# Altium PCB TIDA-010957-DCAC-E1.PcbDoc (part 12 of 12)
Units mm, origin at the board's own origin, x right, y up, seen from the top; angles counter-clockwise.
Board outline 300 x 300 mm, 4 copper layers (Top Layer, Layer 1, Layer 2, Bottom Layer), stack 1.787 mm thick; 1159 components, 619 nets, 3431 pads, 2942 vias.
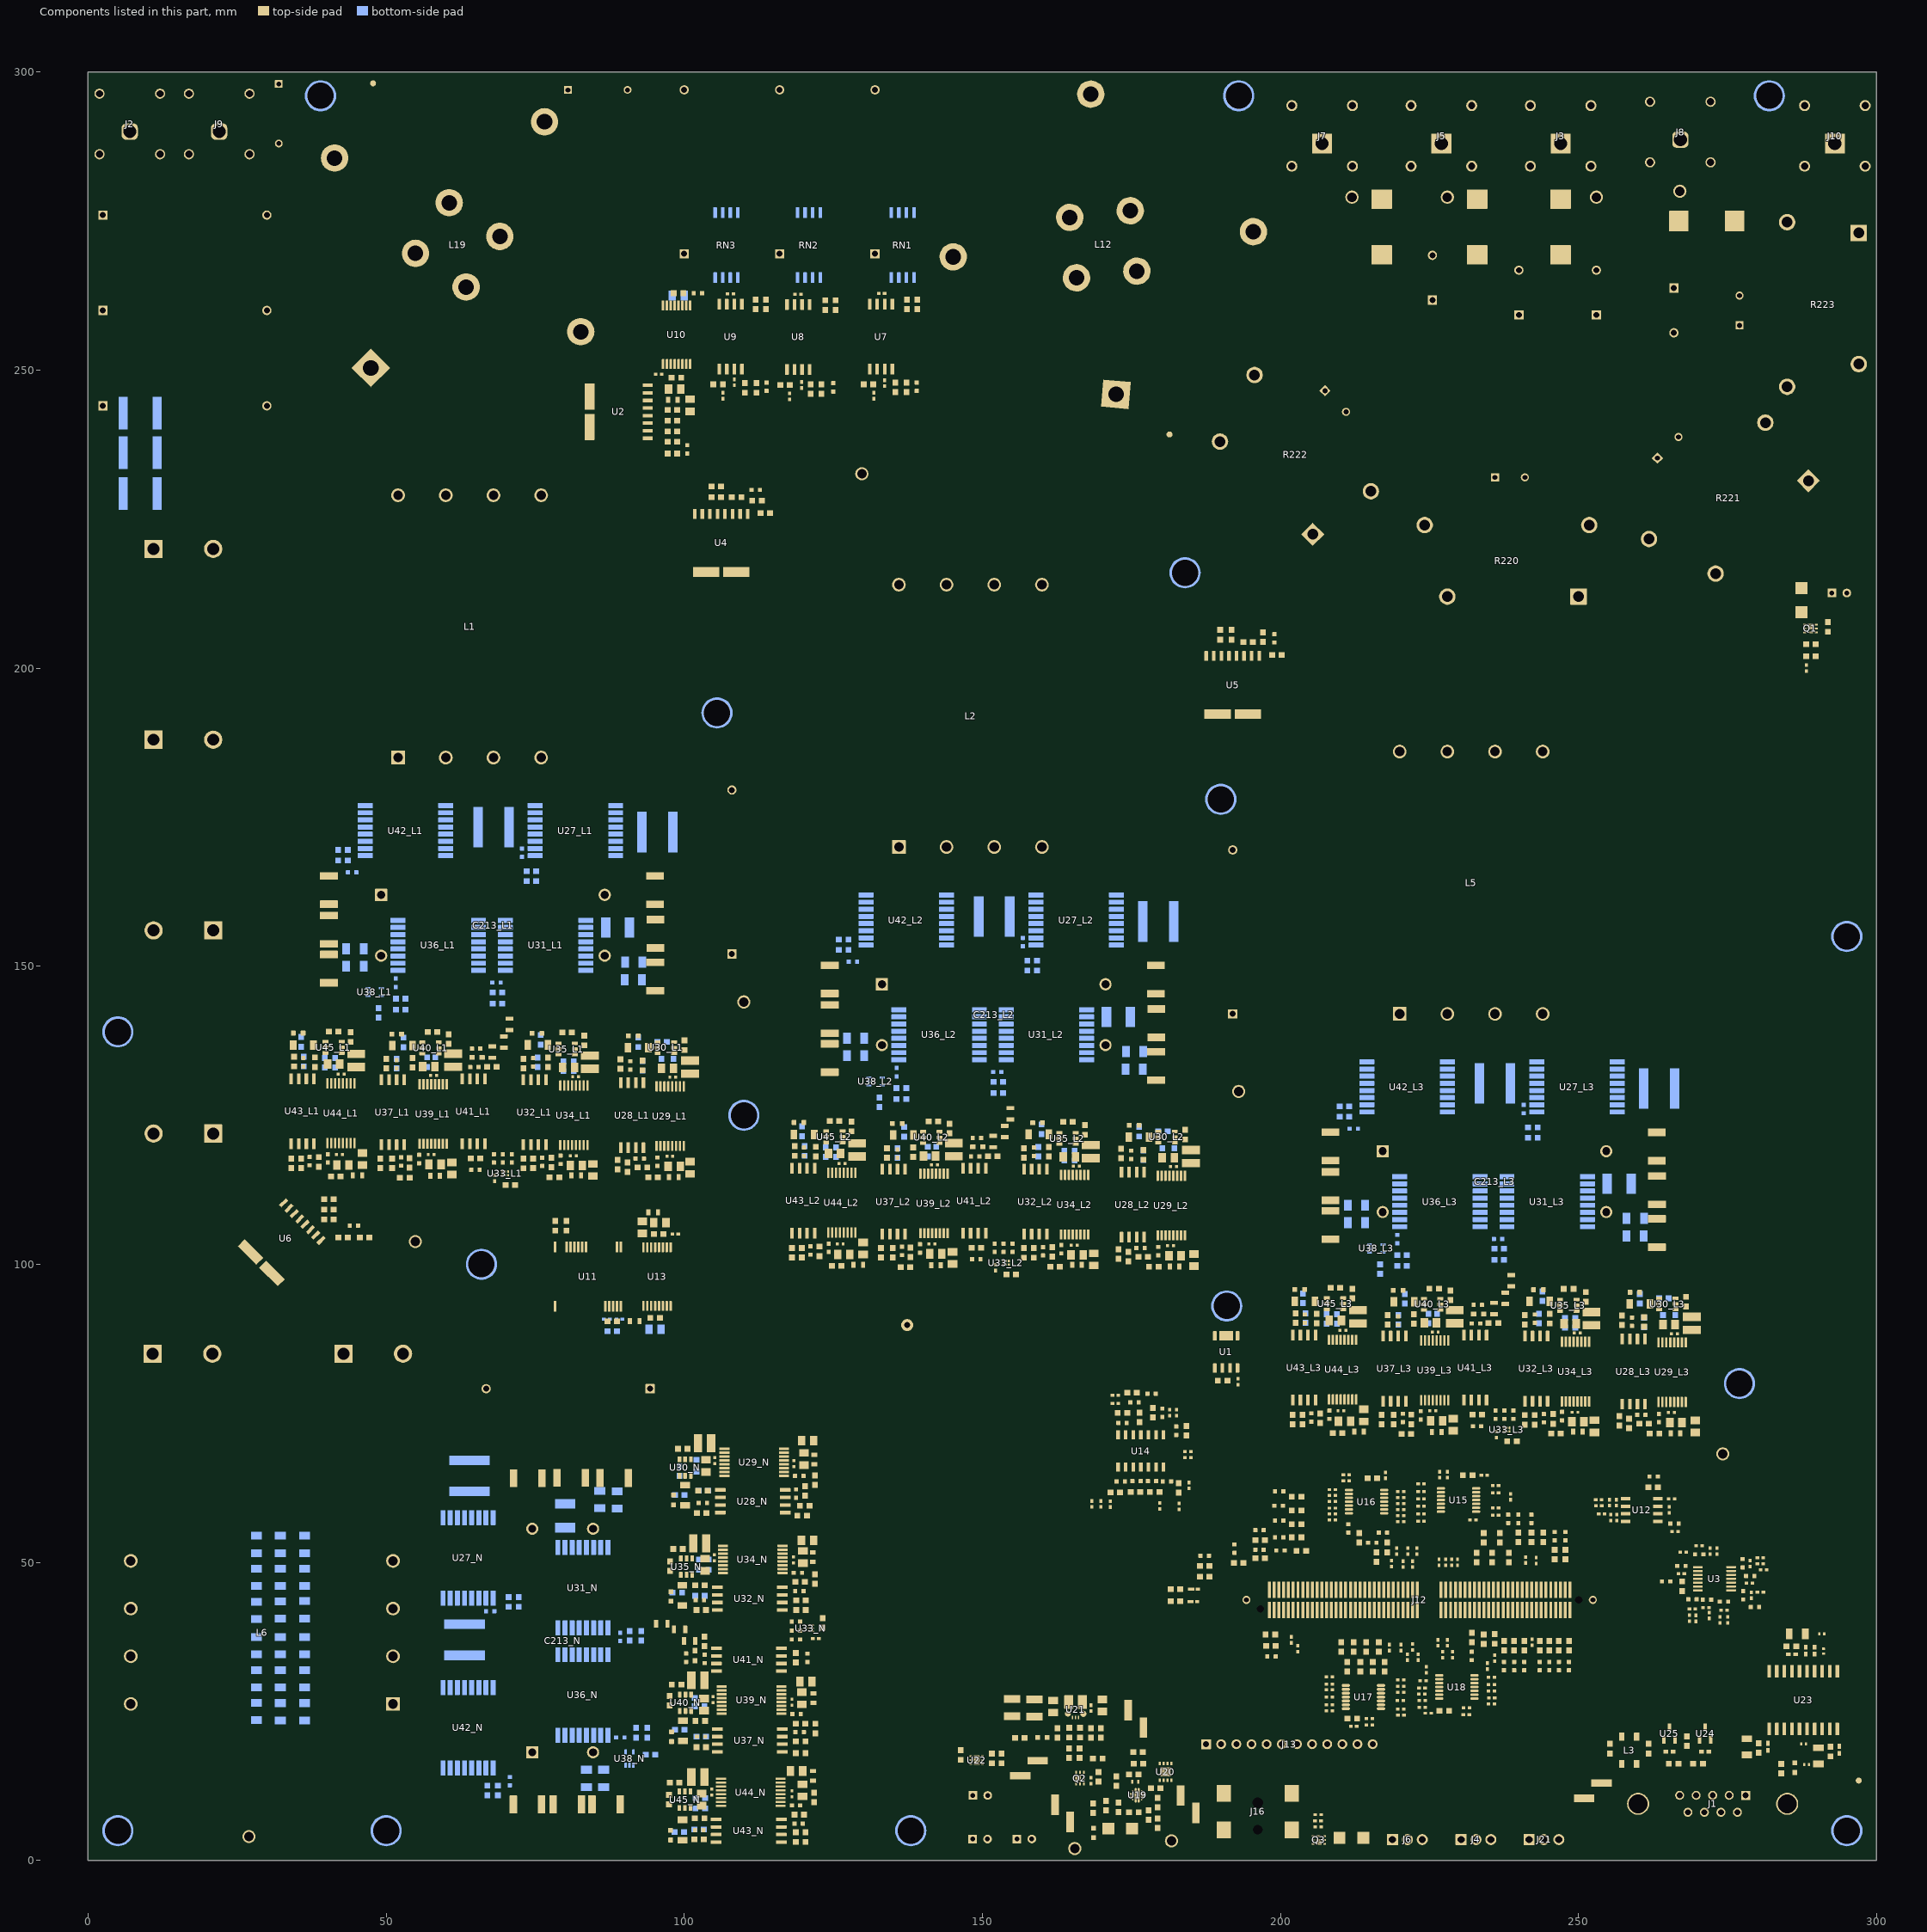
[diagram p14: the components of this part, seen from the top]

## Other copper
Top Layer:
  pour cut-out: 287.687,154.526 ccw(c294.987,154.526) 294.987,147.226 ccw(c294.987,154.526) 302.287,154.526 ccw(c294.987,154.526) 294.987,161.826 ccw(c294.987,154.526)
  pour cut-out: 185.787,295.826 ccw(c193.087,295.826) 193.087,288.526 ccw(c193.087,295.826) 200.387,295.826 ccw(c193.087,295.826) 193.087,303.126 ccw(c193.087,295.826)
  pour cut-out: 176.787,215.826 ccw(c184.087,215.826) 184.087,208.526 ccw(c184.087,215.826) 191.387,215.826 ccw(c184.087,215.826) 184.087,223.126 ccw(c184.087,215.826)
  pour cut-out: 98.287,192.326 ccw(c105.587,192.326) 105.587,185.026 ccw(c105.587,192.326) 112.887,192.326 ccw(c105.587,192.326) 105.587,199.626 ccw(c105.587,192.326)
  pour cut-out: 182.762,177.641 ccw(c190.062,177.641) 190.062,170.341 ccw(c190.062,177.641) 197.362,177.641 ccw(c190.062,177.641) 190.062,184.941 ccw(c190.062,177.641)
  pour cut-out: 287.787,4.826 ccw(c295.087,4.826) 295.087,-2.474 ccw(c295.087,4.826) 302.387,4.826 ccw(c295.087,4.826) 295.087,12.126 ccw(c295.087,4.826)
  pour cut-out: 102.787,124.826 ccw(c110.087,124.826) 110.087,117.526 ccw(c110.087,124.826) 117.387,124.826 ccw(c110.087,124.826) 110.087,132.126 ccw(c110.087,124.826)
  pour cut-out: 58.787,99.826 ccw(c66.087,99.826) 66.087,92.526 ccw(c66.087,99.826) 73.387,99.826 ccw(c66.087,99.826) 66.087,107.126 ccw(c66.087,99.826)
  pour cut-out: -2.213,4.826 ccw(c5.087,4.826) 5.087,-2.474 ccw(c5.087,4.826) 12.387,4.826 ccw(c5.087,4.826) 5.087,12.126 ccw(c5.087,4.826)
  pour cut-out: 42.487,3.726 ccw(c49.787,3.726) 49.787,-3.574 ccw(c49.787,3.726) 57.087,3.726 ccw(c49.787,3.726) 49.787,11.026 ccw(c49.787,3.726)
  pour cut-out: 130.687,4.526 ccw(c137.987,4.526) 137.987,-2.774 ccw(c137.987,4.526) 145.287,4.526 ccw(c137.987,4.526) 137.987,11.826 ccw(c137.987,4.526)
  pour cut-out: 269.787,79.826 ccw(c277.087,79.826) 277.087,72.526 ccw(c277.087,79.826) 284.387,79.826 ccw(c277.087,79.826) 277.087,87.126 ccw(c277.087,79.826)
  pour cut-out: -2.994,139.199 ccw(c4.306,139.199) 4.306,131.899 ccw(c4.306,139.199) 11.606,139.199 ccw(c4.306,139.199) 4.306,146.499 ccw(c4.306,139.199)
  pour cut-out: 187.246,190.135 186.958,190.135 186.958,193.081 187.246,193.081
  pour cut-out: 101.456,213.97 101.168,213.97 101.168,216.916 101.456,216.916
  pour cut-out: 188.1,99.2 185.8,99.2 183.7,97.1 183.7,87.5 186.1,85.1 188.1,85.1
  pour cut-out: 31.444,95.548 31.241,95.752 33.324,97.835 33.527,97.631
  pour cut-out: 24.174,102.083 23.971,102.286 26.342,104.658 26.546,104.454
  pour cut-out: 19,82 22.5,82 24.096,83.596 24.096,86.404 22.5,88 19,88 17.596,86.596 17.596,83.404
  pour cut-out: 81.97,247.754 81.97,248.042 84.916,248.042 84.916,247.754
  pour cut-out: 81.983,237.968 81.983,238.256 84.929,238.256 84.929,237.968
  pour cut-out: 111.232,214.033 110.944,214.033 110.944,216.979 111.232,216.979
  pour cut-out: 197.032,190.158 196.744,190.158 196.744,193.104 197.032,193.104
  pour cut-out: 7.75,217 14.25,217 14.25,223 7.75,223
  pour cut-out: 7.75,185 14.25,185 14.25,191 7.75,191
  pour cut-out: 7.75,153 14.25,153 14.25,159 7.75,159
  pour cut-out: 7.75,118.936 14.25,118.936 14.25,124.936 7.75,124.936
  pour cut-out: 48.334,80.5 57.834,80.5 57.834,89.463 48.334,89.463
  pour cut-out: 16.5,117.436 26,117.436 26,126.399 16.5,126.399
  pour cut-out: 16.5,215.5 26,215.5 26,224.463 16.5,224.463
  pour cut-out: 16.5,183.5 26,183.5 26,192.463 16.5,192.463
  pour cut-out: 18.5,151.5 24,151.5 26,153.5 26,158.5 24.037,160.463 18.463,160.463 16.5,158.5 16.5,153.5
  text ".Layer_Name" at 169.75,-14.25 h1.52
Layer 1:
  pour cut-out: -3.016,139.284 ccw(c4.284,139.284) 4.284,131.984 ccw(c4.284,139.284) 11.584,139.284 ccw(c4.284,139.284) 4.284,146.584 ccw(c4.284,139.284)
  pour cut-out: 287.74,154.548 ccw(c295.04,154.548) 295.04,147.248 ccw(c295.04,154.548) 302.34,154.548 ccw(c295.04,154.548) 295.04,161.848 ccw(c295.04,154.548)
  pour cut-out: 274.84,295.848 ccw(c282.14,295.848) 282.14,288.548 ccw(c282.14,295.848) 289.44,295.848 ccw(c282.14,295.848) 282.14,303.148 ccw(c282.14,295.848)
  pour cut-out: 185.84,295.848 ccw(c193.14,295.848) 193.14,288.548 ccw(c193.14,295.848) 200.44,295.848 ccw(c193.14,295.848) 193.14,303.148 ccw(c193.14,295.848)
  pour cut-out: 31.884,296.035 ccw(c39.184,296.035) 39.184,288.735 ccw(c39.184,296.035) 46.484,296.035 ccw(c39.184,296.035) 39.184,303.335 ccw(c39.184,296.035)
  pour cut-out: 176.84,215.848 ccw(c184.14,215.848) 184.14,208.548 ccw(c184.14,215.848) 191.44,215.848 ccw(c184.14,215.848) 184.14,223.148 ccw(c184.14,215.848)
  pour cut-out: 287.84,4.848 ccw(c295.14,4.848) 295.14,-2.452 ccw(c295.14,4.848) 302.44,4.848 ccw(c295.14,4.848) 295.14,12.148 ccw(c295.14,4.848)
  pour cut-out: 183.74,93.148 ccw(c191.04,93.148) 191.04,85.848 ccw(c191.04,93.148) 198.34,93.148 ccw(c191.04,93.148) 191.04,100.448 ccw(c191.04,93.148)
  pour cut-out: 102.84,124.848 ccw(c110.14,124.848) 110.14,117.548 ccw(c110.14,124.848) 117.44,124.848 ccw(c110.14,124.848) 110.14,132.148 ccw(c110.14,124.848)
  pour cut-out: 58.84,99.848 ccw(c66.14,99.848) 66.14,92.548 ccw(c66.14,99.848) 73.44,99.848 ccw(c66.14,99.848) 66.14,107.148 ccw(c66.14,99.848)
  pour cut-out: -2.16,4.848 ccw(c5.14,4.848) 5.14,-2.452 ccw(c5.14,4.848) 12.44,4.848 ccw(c5.14,4.848) 5.14,12.148 ccw(c5.14,4.848)
  pour cut-out: 42.54,3.748 ccw(c49.84,3.748) 49.84,-3.552 ccw(c49.84,3.748) 57.14,3.748 ccw(c49.84,3.748) 49.84,11.048 ccw(c49.84,3.748)
  pour cut-out: 130.74,4.548 ccw(c138.04,4.548) 138.04,-2.752 ccw(c138.04,4.548) 145.34,4.548 ccw(c138.04,4.548) 138.04,11.848 ccw(c138.04,4.548)
  pour cut-out: 269.772,79.87 ccw(c277.072,79.87) 277.072,72.57 ccw(c277.072,79.87) 284.372,79.87 ccw(c277.072,79.87) 277.072,87.17 ccw(c277.072,79.87)
  pour cut-out: 185,175 185,181.5 187,183.5 193.5,183.5 195,182 195,175 193,173 187,173
  pour cut-out: 100.5,189 100.5,196.5 102,198 109,198 110.5,196.5 110.5,189 109,187.5 102,187.5
  pour cut-out: 249.7,260.2 249.7,259.3 252.7,256.3 256.4,256.3 256.5,256.4 249.7,263.2
Layer 2:
  pour cut-out: -2.99,139.283 ccw(c4.31,139.283) 4.31,131.983 ccw(c4.31,139.283) 11.61,139.283 ccw(c4.31,139.283) 4.31,146.583 ccw(c4.31,139.283)
  pour cut-out: 287.761,154.533 ccw(c295.061,154.533) 295.061,147.233 ccw(c295.061,154.533) 302.361,154.533 ccw(c295.061,154.533) 295.061,161.833 ccw(c295.061,154.533)
  pour cut-out: 274.861,295.833 ccw(c282.161,295.833) 282.161,288.533 ccw(c282.161,295.833) 289.461,295.833 ccw(c282.161,295.833) 282.161,303.133 ccw(c282.161,295.833)
  pour cut-out: 185.861,295.833 ccw(c193.161,295.833) 193.161,288.533 ccw(c193.161,295.833) 200.461,295.833 ccw(c193.161,295.833) 193.161,303.133 ccw(c193.161,295.833)
  pour cut-out: 176.861,215.833 ccw(c184.161,215.833) 184.161,208.533 ccw(c184.161,215.833) 191.461,215.833 ccw(c184.161,215.833) 184.161,223.133 ccw(c184.161,215.833)
  pour cut-out: 287.861,4.833 ccw(c295.161,4.833) 295.161,-2.467 ccw(c295.161,4.833) 302.461,4.833 ccw(c295.161,4.833) 295.161,12.133 ccw(c295.161,4.833)
  pour cut-out: 183.761,93.133 ccw(c191.061,93.133) 191.061,85.833 ccw(c191.061,93.133) 198.361,93.133 ccw(c191.061,93.133) 191.061,100.433 ccw(c191.061,93.133)
  pour cut-out: 102.861,124.833 ccw(c110.161,124.833) 110.161,117.533 ccw(c110.161,124.833) 117.461,124.833 ccw(c110.161,124.833) 110.161,132.133 ccw(c110.161,124.833)
  pour cut-out: 58.861,99.833 ccw(c66.161,99.833) 66.161,92.533 ccw(c66.161,99.833) 73.461,99.833 ccw(c66.161,99.833) 66.161,107.133 ccw(c66.161,99.833)
  pour cut-out: -2.139,4.833 ccw(c5.161,4.833) 5.161,-2.467 ccw(c5.161,4.833) 12.461,4.833 ccw(c5.161,4.833) 5.161,12.133 ccw(c5.161,4.833)
  pour cut-out: 42.561,3.733 ccw(c49.861,3.733) 49.861,-3.567 ccw(c49.861,3.733) 57.161,3.733 ccw(c49.861,3.733) 49.861,11.033 ccw(c49.861,3.733)
  pour cut-out: 130.761,4.533 ccw(c138.061,4.533) 138.061,-2.767 ccw(c138.061,4.533) 145.361,4.533 ccw(c138.061,4.533) 138.061,11.833 ccw(c138.061,4.533)
  pour cut-out: 269.794,79.856 ccw(c277.094,79.856) 277.094,72.556 ccw(c277.094,79.856) 284.394,79.856 ccw(c277.094,79.856) 277.094,87.156 ccw(c277.094,79.856)
  pour cut-out: 100.5,189 100.5,196.5 102,198 109,198 110.5,196.5 110.5,189 109,187.5 102,187.5
  pour cut-out: 185,175 185,187.5 205,187.5 205,182.5 195.5,173 187,173
Bottom Layer:
  pour cut-out: 287.687,154.526 ccw(c294.987,154.526) 294.987,147.226 ccw(c294.987,154.526) 302.287,154.526 ccw(c294.987,154.526) 294.987,161.826 ccw(c294.987,154.526)
  pour cut-out: 185.787,295.826 ccw(c193.087,295.826) 193.087,288.526 ccw(c193.087,295.826) 200.387,295.826 ccw(c193.087,295.826) 193.087,303.126 ccw(c193.087,295.826)
  pour cut-out: 176.787,215.826 ccw(c184.087,215.826) 184.087,208.526 ccw(c184.087,215.826) 191.387,215.826 ccw(c184.087,215.826) 184.087,223.126 ccw(c184.087,215.826)
  pour cut-out: 98.287,192.326 ccw(c105.587,192.326) 105.587,185.026 ccw(c105.587,192.326) 112.887,192.326 ccw(c105.587,192.326) 105.587,199.626 ccw(c105.587,192.326)
  pour cut-out: 182.731,177.657 ccw(c190.031,177.657) 190.031,170.357 ccw(c190.031,177.657) 197.331,177.657 ccw(c190.031,177.657) 190.031,184.957 ccw(c190.031,177.657)
  pour cut-out: 287.787,4.826 ccw(c295.087,4.826) 295.087,-2.474 ccw(c295.087,4.826) 302.387,4.826 ccw(c295.087,4.826) 295.087,12.126 ccw(c295.087,4.826)
  pour cut-out: 102.787,124.826 ccw(c110.087,124.826) 110.087,117.526 ccw(c110.087,124.826) 117.387,124.826 ccw(c110.087,124.826) 110.087,132.126 ccw(c110.087,124.826)
  pour cut-out: 58.787,99.826 ccw(c66.087,99.826) 66.087,92.526 ccw(c66.087,99.826) 73.387,99.826 ccw(c66.087,99.826) 66.087,107.126 ccw(c66.087,99.826)
  pour cut-out: -2.213,4.826 ccw(c5.087,4.826) 5.087,-2.474 ccw(c5.087,4.826) 12.387,4.826 ccw(c5.087,4.826) 5.087,12.126 ccw(c5.087,4.826)
  pour cut-out: 42.487,3.726 ccw(c49.787,3.726) 49.787,-3.574 ccw(c49.787,3.726) 57.087,3.726 ccw(c49.787,3.726) 49.787,11.026 ccw(c49.787,3.726)
  pour cut-out: 130.687,4.526 ccw(c137.987,4.526) 137.987,-2.774 ccw(c137.987,4.526) 145.287,4.526 ccw(c137.987,4.526) 137.987,11.826 ccw(c137.987,4.526)
  pour cut-out: 269.787,79.826 ccw(c277.087,79.826) 277.087,72.526 ccw(c277.087,79.826) 284.387,79.826 ccw(c277.087,79.826) 277.087,87.126 ccw(c277.087,79.826)
  pour cut-out: 27.5,273.4 27.5,278 32.5,278 32.5,273.4
  pour cut-out: 188.1,99.1 185.7,99.1 183.7,97.1 183.7,87.5 186.1,85.1 188.1,85.1
  pour cut-out: 16.579,215.497 26.079,215.497 26.079,224.46 16.579,224.46
  pour cut-out: 16.579,183.497 26.079,183.497 26.079,192.46 16.579,192.46
  pour cut-out: 19.003,151.497 23.497,151.497 26,154 26,158 23.54,160.46 18.96,160.46 16.5,158 16.5,154
  pour cut-out: 16.579,117.434 26.079,117.434 26.079,126.397 16.579,126.397
  pour cut-out: 6.346,80.5 15.846,80.5 15.846,89.463 6.346,89.463
  text ".Layer_Name" at -20.344,-20.806 h1.52

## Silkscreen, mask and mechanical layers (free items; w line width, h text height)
Top Overlay:
  circle w0.254: c0.7,8.5 r0.5
  circle w0.254: c200,192.5 r0.5
  circle w0.254: c116,220.5 r0.5
  circle w0.254: c32,235.5 r0.5
  lines w0.254: 10,10 49,10 49,68 10,68 10,10 ; 35.7,187.2 35.7,226.2 93.7,226.2 93.7,187.2 35.7,187.2 ; 119.7,172.1 119.7,211.1 177.7,211.1 177.7,172.1 119.7,172.1 ; 203.7,144.1 203.7,183.1 261.7,183.1 261.7,144.1 203.7,144.1
  text "'.PRJ_Number'-.PCB_Rev" at 137.1,48.4 h5
  text ".Layer_Name" at -20.344,-20.806 h1.52
Bottom Overlay:
  text ".Layer_Name" at -20.344,-20.806 h1.52
Top Paste:
  text ".Layer_Name" at 169.75,-14.25 h1.52
Bottom Paste:
  text ".Layer_Name" at -20.344,-20.806 h1.52
Top Solder:
  rectangle: 187,89.5 195,96.5
  rectangle: 278,292 286,299
  rectangle: 35,292 43,299
  text ".Layer_Name" at 169.75,-14.25 h1.52
  text ".Layer_Name" at 169.75,-14.25 h1.52
Bottom Solder:
  text ".Layer_Name" at -20.344,-20.806 h1.52
Drill Guide:
  text ".Layer_Name" at 169.75,-14.25 h1.52
M1 Board Outline:
  lines w1: 0,0 0,300 300,300 300,0 0,0 ; 105,77 115,77 115,87 105,87 105,77
  text ".Layer_Name" at -20.344,-20.806 h1.52
M2 Board Dimensions:
  rectangle: -31.825,-9.16 -22.3,-5.985
  rectangle: -35,-5.985 -31.825,-2.81
  lines w0.178: -35,-5.985 -9.6,-5.985 ; -31.825,-9.16 -31.825,-2.81 ; -28.65,-9.16 -28.65,-2.81 ; -22.3,-9.16 -22.3,-2.81 ; -15.95,-9.16 -15.95,-2.81 ; -35,-9.16 -35,-2.81 -9.6,-2.81 -9.6,-9.16 -35,-9.16
  text ".Layer_Name" at -20.344,-20.806 h1.52
M3 3D STEP Top:
  text ".Layer_Name" at -20.344,-20.806 h1.52
M4 3D STEP Bottom:
  text ".Layer_Name" at -20.344,-20.806 h1.52
M5 Assembly Top:
  lines w0.254: -42.417,-22.626 125.223,-22.626 ; -42.417,-17.462 125.274,-17.462 ; -42.417,-12.297 -42.417,-27.791 59.31,-27.791 125.274,-27.791 125.274,-12.297 -42.404,-12.297 -42.404,-27.791 -2.386,-27.791 ; 20.194,-27.791 20.194,-12.297 ; 52.376,-17.462 52.376,-12.297 ; 73.712,-17.462 73.712,-12.297 ; 89.511,-27.956 89.511,-22.804
  text "PLOT NAME =" at 55.993,178.485 h1.52 r270
  text "COMPONENTS MARKED 'DNP' SHOULD NOT BE POPULATED." at -5.701,-7.09 h1.52
  text "ASSEMBLY VARIANT:" at -5.714,-10.024 h1.52
  text ".VariantName" at 20.601,-10.024 h1.52
  text "PCB VIEWED FROM TOP SIDE" at -40.804,-15.654 h1.52
  text "BOARD #:" at 22.099,-15.654 h1.52
  text ".PRJ_Number" at 35.955,-15.654 h1.52
  text "REV:" at 57.405,-15.654 h1.52
  text ".PCB_Rev" at 64.809,-15.654 h1.52
  text "SVN REV:" at 78.69,-15.654 h1.52
  text ".VersionControl_RevNumber" at 91.543,-15.654 h1.52
  text ".plot_File_Name" at -20.344,-26.034 h1.52
  text "GENERATED    :" at 22.15,-26.034 h1.52
  text ".Print_Date" at 44.235,-26.034 h1.52
  text ".Print_Time" at 62.752,-26.034 h1.52
  text "TEXAS INSTRUMENTS" at 94.87,-26.034 h1.52
M6 Assembly Bottom:
  lines w0.254: -42.43,-17.474 125.261,-17.474 ; -42.379,-22.639 125.261,-22.639 ; 9.132,-17.474 9.132,-12.31 ; 30.468,-17.474 30.468,-12.31 ; 54.058,144.347 59.21,144.347 ; 62.65,-27.804 62.65,-12.31 ; 85.231,-27.804 125.249,-27.804 125.249,-12.31 -42.43,-12.31 -42.43,-27.804 23.534,-27.804 125.261,-27.804 125.261,-12.31
  text "TEXAS INSTRUMENTS" at 55.98,149.707 h1.52 r270
  text "COMPONENTS MARKED 'DNP' SHOULD NOT BE POPULATED." at 119.991,-7.077 h1.52
  text ".VariantName" at 93.473,-10.024 h1.52
  text "ASSEMBLY VARIANT:" at 119.864,-10.024 h1.52
  text ".VersionControl_RevNumber" at -8.698,-15.667 h1.52
  text "SVN REV:" at 4.154,-15.667 h1.52
  text ".PCB_Rev" at 18.035,-15.667 h1.52
  text "REV:" at 25.439,-15.667 h1.52
  text ".PRJ_Number" at 46.89,-15.667 h1.52
  text "BOARD #:" at 60.745,-15.667 h1.52
  text "PCB VIEWED FROM BOTTOM SIDE" at 123.648,-15.667 h1.52
  text ".Print_Time" at 20.093,-26.047 h1.52
  text ".Print_Date" at 38.609,-26.047 h1.52
  text "GENERATED    :" at 60.694,-26.047 h1.52
  text ".plot_File_Name" at 103.189,-26.047 h1.52
  text "PLOT NAME =" at 123.648,-26.047 h1.52
M9 Title Sheet:
  drawing of 63 lines, arcs and shapes, not listed
  text "1" at 0.293,467.75 h1.78
  text "2" at 101.766,467.75 h1.78
  text "3" at 203.239,467.75 h1.78
  text "4" at 304.865,467.75 h1.78
  text "5" at 406.423,467.75 h1.78
  text "6" at 507.98,467.75 h1.78
  text "7" at 609.623,467.75 h1.78
  text "8" at 711.096,467.75 h1.78
  text "A" at -46.875,406.841 h1.78
  text "A" at 758.305,406.841 h1.78
  text "B" at -46.875,279.841 h1.78
  text "B" at 758.305,279.841 h1.78
  text "C" at -46.875,152.841 h1.78
  text "C" at 758.305,152.841 h1.78
  text "D" at -46.875,25.841 h1.78
  text "D" at 758.305,25.841 h1.78
  text "PROJECT TITLE:" at 679.946,7.823 h1.14
  text ".PRJ_Title" at 681.216,4.436 h1.78
  text "DESIGNED FOR:" at 679.946,0.177 h1.14
  text ".PRJ_Customer" at 681.216,-3.379 h1.78
  text "FILE NAME:" at 679.946,-7.443 h1.14
  text ".PCB_File_Name_No_Path" at 681.216,-10.491 h1.78
  text "Texas Instruments (TI) and/or its licensors do not warrant the accuracy or completeness of this specification" at 553.721,-14.601 h1.14
  text "ENGINEER:" at 679.946,-14.809 h1.14
  text "LAYOUT BY:" at 718.173,-14.809 h1.14
  text "or any information contained therein. TI and/or its licensors do not warrant that this design will meet" at 552.579,-17.463 h1.14
  text ".PRJ_Engineer" at 681.216,-18.746 h1.78
  text ".PCB_Layout" at 719.456,-18.746 h1.78
  text "the specifications, will be suitable for your application or fit for any particular purpose, or will operate in" at 552.579,-20.325 h1.14
  text ".Layer_Name" at -20.344,-20.806 h1.52
  text "ALTIUM DESIGNER VERSION:" at 718.173,-22.683 h1.14
  text "an implementation. TI and/or its licensors do not warrant that the design is production worthy. You should" at 552.579,-23.187 h1.14
  text "completely validate and test your design implementation to confirm the system functionality for your application." at 553.721,-26.048 h1.14
  text ".print_Scale" at 681.216,-26.069 h1.78
  text ".Application_BuildNumber" at 719.456,-26.069 h1.78
  text "1" at 0.293,-32.503 h1.78
  text "2" at 101.766,-32.503 h1.78
  text "3" at 203.239,-32.503 h1.78
  text "4" at 304.865,-32.503 h1.78
  text "5" at 406.423,-32.503 h1.78
  text "6" at 507.98,-32.503 h1.78
  text "7" at 609.623,-32.503 h1.78
  text "8" at 711.096,-32.503 h1.78
M10 Fab Notes:
  drawing of 189 lines, arcs and shapes, not listed
  text "DESIGN INFORMATION" at 706.376,162.675 h1.52
  text "MIN. TRACK WIDTH:" at 690.004,159.319 h1.52
  text "8" at 717.848,159.32 h1.52
  text "MIL" at 721.779,159.319 h1.52
  text "MIN. CLEARANCE:" at 690.004,156.167 h1.52
  text "7.874" at 713.5,156.167 h1.52
  text "MIL" at 721.779,156.167 h1.52
  text "MIN. VIA PAD SIZE:" at 690.004,153.014 h1.52
  text "24" at 717.087,153.014 h1.52
  text "MIL" at 721.779,153.014 h1.52
  text "0.05mm (2MIL)" at 707.657,149.714 h1.52
  text "MINIMUM ANNULAR RING" at 681.641,149.506 h1.52
  text "EXTERNAL" at 725.64,149.506 h1.52
  text "PER" at 686.721,146.708 h1.52
  text "IPC-D-275 CLASS 2 LEVEL C" at 692.309,146.708 h1.52
  text "MIL, HOLES" at 730.11,144.156 h1.52
  text "+/-" at 720.142,143.938 h1.52
  text "+/-" at 741.834,143.938 h1.52
  text "REGISTRATION TOLERANCES:" at 681.641,143.911 h1.52
  text "METAL" at 712.116,143.911 h1.52
  text "5" at 726.751,143.911 h1.52
  text "3" at 747.909,143.911 h1.52
  text "MIL" at 750.862,143.911 h1.52
  text "HOLE SIZE TOLERANCE (UNLESS OTHERWISE SPECIFIED):" at 681.641,141.414 h1.52
  text "+/-" at 741.834,141.341 h1.52
  text "3" at 747.909,141.314 h1.52
  text "MIL" at 750.862,141.314 h1.52
  text "MATERIAL:" at 679.742,137.818 h1.52
  text "FR-4 High Tg" at 704.798,134.553 h1.52
  text "X" at 701.129,134.35 h1.52
  text "FR-4" at 690.436,134.235 h1.52
  text "OTHER" at 728.231,134.235 h1.52
  text "62 MIL (1.6mm) +/-10%" at 698.566,130.602 h1.52
  text "X" at 728.1,130.6 h1.52
  text "2mm" at 742.287,130.414 h1.52
  text "THICKNESS:" at 681.641,130.394 h1.52
  text "OTHER" at 731.203,130.394 h1.52
  text "TOLERANCE:" at 681.641,126.88 h1.52
  text "X" at 703.187,126.88 h1.52
  text "ANSI IPC-6012 TYPE 3 CLASS 2" at 707.708,126.88 h1.52
  text "OTHER +/-" at 707.708,123.218 h1.52
  text "BOW & TWIST:" at 681.641,119.53 h1.52
  text "X" at 703.187,119.53 h1.52
  text "ANSI IPC-6012 TYPE 3 CLASS 2" at 707.708,119.53 h1.52
  text "OTHER +/-" at 707.708,115.804 h1.52
  text "DRILLING:" at 679.742,112.486 h1.52
  text "NC_DRILL FILES" at 724.472,109.815 h1.52
  text "REFERENCE:" at 681.641,109.715 h1.52
  text "X" at 698.335,109.712 h1.52
  text "AS SHOWN" at 702.856,109.715 h1.52
  text "X" at 721.221,109.715 h1.52
  text "OTHER" at 732.041,106.101 h1.52
  text "PTH COPPER THICKNESS:" at 681.633,106.012 h1.52
  text "X" at 710.57,106.012 h1.52
  text "20-30 um" at 713.821,106.012 h1.52
  text "BOARD FINISH:" at 679.742,102.263 h1.52
  text "SILKSCREEN:" at 683.685,99.466 h1.52
  text "X" at 708.013,99.466 h1.52
  text "TOP" at 710.984,99.466 h1.52
  text "X" at 720.967,99.466 h1.52
  text "BOTTOM" at 723.964,99.466 h1.52
  text "SILKSCREEN COLOR:" at 683.685,95.524 h1.52
  text "X" at 707.987,95.524 h1.52
  text "WHITE" at 710.984,95.524 h1.52
  text "OTHER" at 723.964,95.524 h1.52
  text "X" at 711.315,91.88 h1.52
  text "GREEN" at 714.312,91.88 h1.52
  text "OTHER" at 730.009,91.88 h1.52
  text "SOLDER RESIST COLOR:" at 683.685,91.706 h1.52
  text "X" at 711.315,87.962 h1.52
  text "MATTE" at 714.312,87.962 h1.52
  text "SEMI-GLOSS" at 729.997,87.946 h1.52
  text "IMMERSION GOLD (ENIG)" at 706.692,83.574 h1.52
  text "ENEPIG" at 740.665,83.39 h1.52
  text "SURFACE FINISH:" at 679.742,83.365 h1.52
  text "X" at 702.171,83.365 h1.52
  text "IMM. TIN/SILVER OR EQUIV" at 688.113,79.877 h1.52
  text "OTHER" at 724.472,79.777 h1.52
  text "ARRAY/PANEL:" at 679.742,75.831 h1.52
  text "CUT AND TRIM PER M1 BOARD OUTLINE" at 706.692,75.622 h1.52
  text "N.C. ROUTE" at 706.692,72.168 h1.52
  text "X" at 724.167,72.168 h1.52
  text "V. SCORE" at 728.688,72.168 h1.52
  text "CERTIFICATION:" at 679.742,68.888 h1.52
  text "MATERIALS AND WORKMANSHIP FOR ALL PCBS" at 698.157,68.888 h1.52
  text "TO MEET OR EXCEED THE REQUIREMENTS OF:" at 698.157,66.499 h1.52
  text "X" at 688.95,63.232 h1.52
  text "ANSI IPC-A-600F CLASS ->" at 692.201,63.232 h1.52
  text "X" at 734.06,63.232 h1.52
  text "2" at 736.854,63.232 h1.52
  text "1" at 728.853,63.194 h1.52
  text "3" at 745.846,63.194 h1.52
  text "X" at 709.575,59.481 h1.52
  text "RoHS" at 712.826,59.481 h1.52
  text "OTHER" at 729.194,59.481 h1.52
  text "PER ORDER" at 739.279,59.481 h1.52
  text "ALL BOARDS MUST MEET OR EXCEED UL94-V0 REQUIREMENTS." at 680.442,55.574 h1.52
  text "PCB MUST BEAR THE UL94V-0 UL REGISTERED MATERIAL ID NUMBER" at 680.442,52.626 h1.52
  text "ADDITIONAL REQUIREMENTS:" at 679.742,48.322 h1.52
  text "MICROSECTION:" at 681.641,45.601 h1.52
  text "YES" at 704.647,45.601 h1.52
  text "REQUIRED" at 726.529,41.935 h1.52
  text "BARE BOARD ELEC. TEST:" at 681.641,41.863 h1.52
  text "NONE" at 714.807,41.863 h1.52
  text "X" at 723.532,41.863 h1.52
  text "PER ORDER" at 741.566,41.863 h1.52
  text "XX MIL VIAS REQUIRE NON-CONDUCTIVE FILL AND PLANARIZE" at 685.912,36.657 h1.5
  text "XX MIL VIAS REQUIRE CONDUCTIVE FILL AND PLANARIZE" at 686.116,34.016 h1.52
  text "OUTER XX MIL TRACES REQUIRE 50 OHM SINGLE-ENDED IMPEDANCE" at 686.091,29.866 h1.47
  text "LAYER 2 & 3 (INNER LAYERS) XX MIL WIDE, XX MIL SPACE / TRACES REQUIRE 100 OHM DIFFERENTIAL IMPEDANCE" at 685.887,23.879 h1.52
  text ".Layer_Name" at -20.344,-20.806 h1.52
M11 Gerber Information:
  lines w0.254: -42.417,-22.626 125.223,-22.626 ; -42.417,-17.462 125.274,-17.462 ; -42.417,-12.297 -42.417,-27.791 59.31,-27.791 125.274,-27.791 125.274,-12.297 -42.404,-12.297 -42.404,-27.791 -2.386,-27.791 ; 20.194,-27.791 20.194,-12.297 ; 52.376,-17.462 52.376,-12.297 ; 73.712,-17.462 73.712,-12.297 ; 89.511,-27.956 89.511,-22.804
  text "LAYER NAME =" at 149.29,-14.25 h1.52
  text "ALL ARTWORK VIEWED FROM TOP SIDE" at -40.804,-15.654 h1.52
  text "BOARD #:" at 22.099,-15.654 h1.52
  text ".PRJ_Number" at 35.955,-15.654 h1.52
  text "REV:" at 57.405,-15.654 h1.52
  text ".PCB_Rev" at 64.809,-15.654 h1.52
  text "SVN REV:" at 78.69,-15.654 h1.52
  text ".VersionControl_RevNumber" at 91.543,-15.654 h1.52
  text "PLOT NAME =" at 149.29,-19.478 h1.52
  text ".plot_File_Name" at -20.344,-26.034 h1.52
  text "GENERATED    :" at 22.15,-26.034 h1.52
  text ".Print_Date" at 44.235,-26.034 h1.52
  text ".Print_Time" at 62.752,-26.034 h1.52
  text "TEXAS INSTRUMENTS" at 94.87,-26.034 h1.52
M12 Stackup:
  drawing of 295 lines, arcs and shapes, not listed
  text "Layer" at 639.469,458.524 h1.52
  text "Name" at 649.88,458.524 h1.52
  text "Material" at 673.496,458.524 h1.52
  text "Thickness" at 695.334,458.524 h1.52
  text "Constant" at 711.84,458.524 h1.52
  text "Board Layer Stack" at 726.314,458.524 h1.52
  text "Top Overlay" at 649.88,455.476 h1.52
  text "Top Solder" at 649.88,452.428 h1.52
  text "Solder Resist" at 673.496,452.428 h1.52
  text "0,40mil" at 695.334,452.428 h1.52
  text "3.5" at 711.84,452.428 h1.52
  text "1" at 639.469,449.38 h1.52
  text "Top Layer" at 649.88,449.38 h1.52
  text "1,40mil" at 695.334,449.38 h1.52
  text "Dielectric 1" at 649.88,446.332 h1.52
  text "PP-006" at 673.496,446.332 h1.52
  text "2,80mil" at 695.334,446.332 h1.52
  text "4.1" at 711.84,446.332 h1.52
  text "2" at 639.469,443.284 h1.52
  text "Layer 1" at 649.88,443.284 h1.52
  text "CF-004" at 673.496,443.284 h1.52
  text "1,38mil" at 695.334,443.284 h1.52
  text "Dielectric1" at 649.88,440.236 h1.52
  text "FR-4 High Tg" at 673.496,440.236 h1.52
  text "59,20mil" at 695.334,440.236 h1.52
  text "4.8" at 711.84,440.236 h1.52
  text "3" at 639.469,437.188 h1.52
  text "Layer 2" at 649.88,437.188 h1.52
  text "CF-004" at 673.496,437.188 h1.52
  text "1,38mil" at 695.334,437.188 h1.52
  text "Dielectric 2" at 649.88,434.14 h1.52
  text "PP-006" at 673.496,434.14 h1.52
  text "2,80mil" at 695.334,434.14 h1.52
  text "4.1" at 711.84,434.14 h1.52
  text "4" at 639.469,431.092 h1.52
  text "Bottom Layer" at 649.88,431.092 h1.52
  text "1,40mil" at 695.334,431.092 h1.52
  text "Bottom Solder" at 649.88,428.044 h1.52
  text "Solder Resist" at 673.496,428.044 h1.52
  text "0,40mil" at 695.334,428.044 h1.52
  text "3.5" at 711.84,428.044 h1.52
  text "Bottom Overlay" at 649.88,424.996 h1.52
  text ".Layer_Name" at 169.75,-14.25 h1.52
M13 Component Bodies Top:
  text ".Layer_Name" at -20.344,-20.806 h1.52
M14 Component Bodies Bottom:
  text ".Layer_Name" at -20.344,-20.806 h1.52
M15 Courtyards Top:
  text ".Layer_Name" at -20.344,-20.806 h1.52
M16 Courtyards Bottom:
  text ".Layer_Name" at -20.344,-20.806 h1.52
Drill Drawing:
  text ".Layer_Name" at -20.344,-20.806 h1.52
M17 Embedded Cavity:
  text ".Layer_Name" at -20.344,-20.806 h1.52
M18 Embedded Assembly:
  text ".Layer_Name" at -20.344,-20.806 h1.52
M19 Embedded Keepout:
  text ".Layer_Name" at -20.09,-20.552 h1.52
Mechanical Drilling Heatsink:
  circle w0.25: c38.975,296 r0.025
  circle w0.25: c281.975,296 r0.025
  circle w0.25: c192.975,296 r0.025
  circle w0.25: c294.975,155 r0.025
  circle w0.25: c183.975,216 r0.025
  circle w0.25: c189.975,178 r0.025
  circle w0.25: c105.475,192.5 r0.025
  circle w0.25: c190.975,93 r0.025
  circle w0.25: c276.975,80 r0.025
  circle w0.25: c109.975,125 r0.025
  circle w0.25: c4.975,139 r0.025
  circle w0.25: c65.975,100 r0.025
  circle w0.25: c294.975,5 r0.025
  circle w0.25: c137.975,5 r0.025
  circle w0.25: c49.975,5 r0.025
  circle w0.25: c4.975,5 r0.025
  circle w0.25: c191,93 r1.414
  circle w0.25: c110,125 r1.414
  circle w0.25: c105.5,192.5 r1.414
  circle w0.25: c190,178 r1.414
  circle w0.25: c184,216 r1.414
  circle w0.25: c282,296 r1.414
  circle w0.25: c193,296 r1.414
  circle w0.25: c39,296 r1.414
  circle w0.25: c5,139 r1.414
  circle w0.25: c66,100 r1.414
  circle w0.25: c295,155 r1.414
  circle w0.25: c277,80 r1.414
  circle w0.25: c295,5 r1.414
  circle w0.25: c138,5 r1.414
  circle w0.25: c50,5 r1.414
  circle w0.25: c5,5 r1.414
  lines w0.254: 0,0 304.5,0 304.5,324.5 0,324.5 0,0

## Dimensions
281.957,295.982 to 304.5,0 on M16 Courtyards Bottom
192.957,296.018 to 304.5,0 on M16 Courtyards Bottom
38.957,296.018 to 0,0 on M16 Courtyards Bottom
183.957,216.018 to 304.5,0 on M16 Courtyards Bottom
294.957,154.982 to 304.5,0 on M16 Courtyards Bottom
189.949,178 to 304.5,0 on M16 Courtyards Bottom
105.5,192.5 to 0,0 on M16 Courtyards Bottom
5,139 to 0,0 on M16 Courtyards Bottom
109.949,125 to 0,0 on M16 Courtyards Bottom
65.993,99.982 to 0,0 on M16 Courtyards Bottom
190.975,92.975 to 304.5,0 on M16 Courtyards Bottom
276.957,79.982 to 304.5,0 on M16 Courtyards Bottom
294.949,5 to 304.5,0 on M16 Courtyards Bottom
137.949,5 to 0,0 on M16 Courtyards Bottom
48.586,5 to 0,0 on M16 Courtyards Bottom
4.993,5.018 to 0,0 on M16 Courtyards Bottom
281.957,295.982 to 0,324.5 on M16 Courtyards Bottom
0,324.5 to 193,296 on M16 Courtyards Bottom
38.975,295.975 to 0,324.5 on M16 Courtyards Bottom
183.993,216.018 to 0,324.5 on M16 Courtyards Bottom
105.449,192.5 to 0,324.5 on M16 Courtyards Bottom
189.949,178 to 0,324.5 on M16 Courtyards Bottom
294.949,155 to 0,0 on M16 Courtyards Bottom
109.949,125 to 0,0 on M16 Courtyards Bottom
4.993,139.018 to 0,0 on M16 Courtyards Bottom
276.949,80 to 0,0 on M16 Courtyards Bottom
0,0 to 190.957,92.982 on M16 Courtyards Bottom
0,0 to 65.949,100 on M16 Courtyards Bottom
295,5 to 0,0 on M16 Courtyards Bottom
138,5 to 0,0 on M16 Courtyards Bottom
0,0 to 50,5 on M16 Courtyards Bottom
5,5 to 0,0 on M16 Courtyards Bottom
304.5,324.5 to 304.5,0 on M16 Courtyards Bottom
0,324.5 to 304.5,324.5 on M16 Courtyards Bottom
-35,-9.16 to -9.6,-9.16 on M2 Board Dimensions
